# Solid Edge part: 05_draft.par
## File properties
Author: edge
Template: jis part.par
Last saved by: edge
Revision: 16
Application: Solid Edge
文書内容のタイプ: 0
Accuracy: 0.990
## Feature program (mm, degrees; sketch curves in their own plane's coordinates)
sketch for "unnamed Protrusion 1" plane through (0, 0, 0) normal (1, 0, 0) x-axis (0, 1, 0)
  line (-50, 0) -> (50, 0)
  line (50, 0) -> (50, 80)
  line (50, 80) -> (-50, 80)
  line (-50, 80) -> (-50, 0)
  dimension (linear) = 50
  dimension (linear) = 50
extrude "unnamed Protrusion 1" add finite 150 symmetric
fillet "丸みづけ_1" radius 15
thinwall "側壁_1"  Thickness = 5 mm
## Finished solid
Body 1: solid body, 19 faces, 48 edges, 32 vertices.
  Faces by surface: plane 11, cylinder 8
  Edges by curve: line 32, circle 16
Bounding box of the edges (mm): 150.000 x 100.000 x 80.000, from (-75, -50, 0) to (75, 50, 80).
Cylindrical faces by radius (mm): R10 x4, R15 x4
Planar faces by outward normal: +x 2, +y 2, +z 2, -x 2, -y 2, -z 1
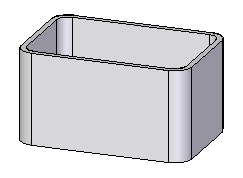
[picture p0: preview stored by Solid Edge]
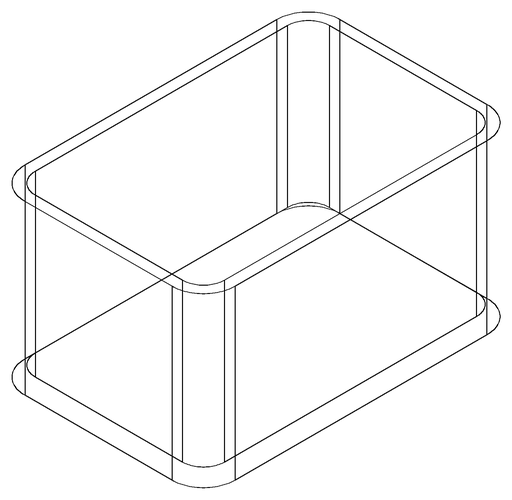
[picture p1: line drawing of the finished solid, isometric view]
